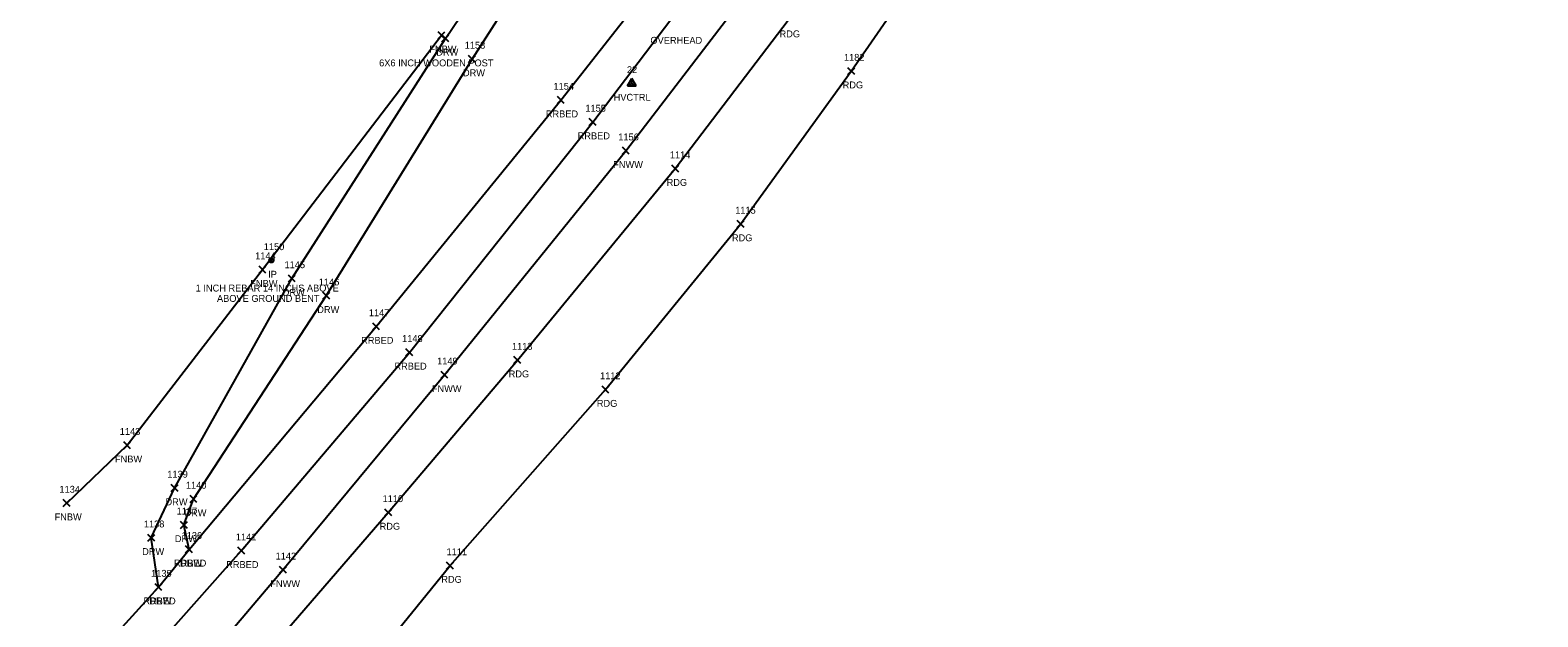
# Model space of a CAD drawing. Extents: x 1508122 to 1515053, y 865012 to 875267.
# Drawn here: x 1509138.2 to 1509575.3, y 866097.6 to 866267.8 of the extents above; entities that cross this region are included whole.
import ezdxf

# ---------------------------------------------------------------- set-up
doc = ezdxf.new("R2010")
doc.units = 0
for name, color, linetype in [('C_A', 7, 'Continuous'), ('C_I', 7, 'Continuous'), ('CPSM', 7, 'Continuous'), ('L_A', 7, 'Continuous'), ('L_C', 7, 'Continuous'), ('L_I', 7, 'Continuous'), ('L_TIC', 7, 'Continuous'), ('LFNC', 7, 'Continuous'), ('M_A', 7, 'Continuous'), ('M_C', 7, 'Continuous'), ('M_I', 7, 'Continuous'), ('MPIR', 7, 'Continuous'), ('P_A', 7, 'Continuous'), ('P_I', 7, 'Continuous'), ('P_TIC', 7, 'Continuous'), ('PEU', 7, 'Continuous'), ('R_A', 7, 'Continuous'), ('R_I', 7, 'Continuous'), ('R_TIC', 7, 'Continuous'), ('RDW', 7, 'Continuous'), ('RRB', 7, 'Continuous'), ('U_A', 7, 'Continuous')]:
    doc.layers.add(name, color=color, linetype=linetype)

msp = doc.modelspace()

# ---------------------------------------------------------------- linework, layer by layer
at = {"layer": 'CPSM'}
for p, q in [((1509311.42, 866251.58), (1509312.67, 866253.74)), ((1509313.92, 866251.58), (1509312.67, 866253.74)), ((1509312.68, 866252.3), (1509312.67, 866253.74)), ((1509311.42, 866251.58), (1509312.68, 866252.3)), ((1509311.42, 866251.58), (1509313.92, 866251.58)), ((1509312.68, 866252.3), (1509312.68, 866252.3)), ((1509312.68, 866252.3), (1509313.92, 866251.58))]:
    msp.add_line(p, q, dxfattribs=at)
at = {"layer": 'L_TIC'}
for points in [[(1509256.48, 866265.27), (1509258.48, 866267.27)], [(1509258.48, 866265.27), (1509256.48, 866267.27)], [(1509309.89, 866231.8), (1509311.89, 866233.8)], [(1509311.89, 866231.8), (1509309.89, 866233.8)], [(1509204.58, 866197.32), (1509206.58, 866199.32)], [(1509206.58, 866197.32), (1509204.58, 866199.32)], [(1509257.33, 866166.82), (1509259.33, 866168.82)], [(1509259.33, 866166.82), (1509257.33, 866168.82)], [(1509165.34, 866146.4), (1509167.34, 866148.4)], [(1509167.34, 866146.4), (1509165.34, 866148.4)], [(1509147.84, 866129.63), (1509149.84, 866131.63)], [(1509149.84, 866129.63), (1509147.84, 866131.63)], [(1509210.5, 866110.27), (1509212.5, 866112.27)], [(1509212.5, 866110.27), (1509210.5, 866112.27)]]:
    msp.add_lwpolyline(points, dxfattribs=at)
at = {"layer": 'LFNC'}
for points in [[(1508724.58, 865616.04), (1508798.39, 865687.75), (1508875.38, 865763.51), (1508931.23, 865818.85), (1508982.18, 865869.29), (1509035.45, 865924.1), (1509094.95, 865982.16), (1509139.87, 866027.02), (1509167.95, 866059.98), (1509211.5, 866111.27), (1509258.33, 866167.82), (1509310.89, 866232.8), (1509348.98, 866282.54), (1509409.27, 866365.5), (1509441.91, 866414.7), (1509478.64, 866471.59), (1509510.32, 866522.25)], [(1509148.84, 866130.63), (1509166.34, 866147.4), (1509205.58, 866198.32), (1509257.48, 866266.27)]]:
    msp.add_lwpolyline(points, dxfattribs=at)
at = {"layer": 'MPIR'}
for radius in [0.625, 0.0833]:
    msp.add_circle((1509208.16, 866200.98), radius, dxfattribs=at)
at = {"layer": 'P_TIC'}
for points in [[(1509375.26, 866254.88), (1509377.26, 866256.88)], [(1509377.26, 866254.88), (1509375.26, 866256.88)], [(1509324.23, 866226.62), (1509326.23, 866228.62)], [(1509326.23, 866226.62), (1509324.23, 866228.62)], [(1509343.16, 866210.55), (1509345.16, 866212.55)], [(1509345.16, 866210.55), (1509343.16, 866212.55)], [(1509278.45, 866171.09), (1509280.45, 866173.09)], [(1509280.45, 866171.09), (1509278.45, 866173.09)], [(1509304, 866162.55), (1509306, 866164.55)], [(1509306, 866162.55), (1509304, 866164.55)], [(1509241.04, 866126.91), (1509243.04, 866128.91)], [(1509243.04, 866126.91), (1509241.04, 866128.91)], [(1509258.93, 866111.51), (1509260.93, 866113.51)], [(1509260.93, 866111.51), (1509258.93, 866113.51)]]:
    msp.add_lwpolyline(points, dxfattribs=at)
at = {"layer": 'PEU'}
for points in [[(1508834.79, 865646.55), (1508872.67, 865695.62), (1508920.37, 865755), (1508947.99, 865790.47), (1508992.59, 865844.04), (1509029.62, 865887.05), (1509074.71, 865938.15), (1509076.21, 865938.91), (1509118.9, 865986.57), (1509166.14, 866040.81), (1509208.36, 866088.99), (1509242.04, 866127.91), (1509279.45, 866172.09), (1509325.23, 866227.62), (1509357.97, 866270.69), (1509379.31, 866300.93), (1509415.81, 866351.46), (1509451.5, 866409.82), (1509485.86, 866467.6), (1509516.97, 866520.33), (1509530.58, 866543.24), (1509548.88, 866575.75)], [(1508854.52, 865631.8), (1508891.73, 865680.86), (1508929.69, 865727.93), (1508966.84, 865774.38), (1509011.87, 865829.05), (1509047.63, 865870.06), (1509091.96, 865920.06), (1509093.12, 865920.34), (1509137.51, 865972.18), (1509182.39, 866021.44), (1509229.98, 866075.59), (1509259.93, 866112.51), (1509305, 866163.55), (1509344.16, 866211.55), (1509376.26, 866255.88), (1509408.52, 866302.52), (1509434.14, 866340.77), (1509471.53, 866399.58), (1509505.51, 866456.15), (1509544.81, 866522.39), (1509575.28, 866574.69)]]:
    msp.add_lwpolyline(points, dxfattribs=at)
at = {"layer": 'R_TIC'}
for points in [[(1509257.58, 866264.37), (1509259.58, 866266.37)], [(1509259.58, 866264.37), (1509257.58, 866266.37)], [(1509265.32, 866258.4), (1509267.32, 866260.4)], [(1509267.32, 866258.4), (1509265.32, 866260.4)], [(1509291.05, 866246.49), (1509293.05, 866248.49)], [(1509293.05, 866246.49), (1509291.05, 866248.49)], [(1509300.29, 866240.12), (1509302.29, 866242.12)], [(1509302.29, 866240.12), (1509300.29, 866242.12)], [(1509213.09, 866194.75), (1509215.09, 866196.75)], [(1509215.09, 866194.75), (1509213.09, 866196.75)], [(1509223.08, 866189.75), (1509225.08, 866191.75)], [(1509225.08, 866189.75), (1509223.08, 866191.75)], [(1509237.52, 866180.83), (1509239.52, 866182.83)], [(1509239.52, 866180.83), (1509237.52, 866182.83)], [(1509247.17, 866173.34), (1509249.17, 866175.34)], [(1509249.17, 866173.34), (1509247.17, 866175.34)], [(1509179.1, 866133.99), (1509181.1, 866135.99)], [(1509181.1, 866133.99), (1509179.1, 866135.99)], [(1509184.58, 866130.81), (1509186.58, 866132.81)], [(1509186.58, 866130.81), (1509184.58, 866132.81)], [(1509181.8, 866123.3), (1509183.8, 866125.3)], [(1509183.8, 866123.3), (1509181.8, 866125.3)], [(1509172.32, 866119.57), (1509174.32, 866121.57)], [(1509174.32, 866119.57), (1509172.32, 866121.57)], [(1509183.3, 866116.22), (1509185.3, 866118.22)], [(1509185.3, 866116.22), (1509183.3, 866118.22)], [(1509183.3, 866116.22), (1509185.3, 866118.22)], [(1509185.3, 866116.22), (1509183.3, 866118.22)], [(1509198.41, 866115.81), (1509200.41, 866117.81)], [(1509200.41, 866115.81), (1509198.41, 866117.81)], [(1509174.42, 866105.26), (1509176.42, 866107.26)], [(1509176.42, 866105.26), (1509174.42, 866107.26)], [(1509174.42, 866105.26), (1509176.42, 866107.26)], [(1509176.42, 866105.26), (1509174.42, 866107.26)]]:
    msp.add_lwpolyline(points, dxfattribs=at)
at = {"layer": 'RDW'}
for points in [[(1509175.42, 866106.26), (1509173.32, 866120.57), (1509180.1, 866134.99), (1509214.09, 866195.75), (1509258.58, 866265.37), (1509297.47, 866322.84), (1509353.91, 866405.07), (1509385.61, 866444.81), (1509414.73, 866486.92), (1509438.11, 866515.54), (1509448.72, 866529.31), (1509457.68, 866545.56), (1509464.46, 866541.85)], [(1509184.3, 866117.22), (1509182.8, 866124.3), (1509185.58, 866131.81), (1509224.08, 866190.75), (1509266.32, 866259.4), (1509302.94, 866316.58), (1509358.12, 866400.23), (1509391.86, 866440.27), (1509422.23, 866480.4), (1509444.66, 866510.88), (1509457.51, 866527.21), (1509464.46, 866541.85)]]:
    msp.add_lwpolyline(points, dxfattribs=at)
at = {"layer": 'RRB'}
for points in [[(1508639.82, 865572.96), (1508703.07, 865634.54), (1508776.82, 865704.61), (1508856.34, 865784.12), (1508912.2, 865838.55), (1508964.7, 865888.82), (1509016.49, 865939.79), (1509080.96, 866005.09), (1509118.28, 866044.61), (1509147.09, 866075.05), (1509175.42, 866106.26), (1509184.3, 866117.22), (1509238.52, 866181.83), (1509292.05, 866247.49), (1509330.87, 866297), (1509389.52, 866377.79), (1509421.76, 866425.85), (1509457.91, 866484.5), (1509492.63, 866543.56), (1509498.04, 866553.04), (1509526.06, 866605.21)], [(1508711.19, 865626.15), (1508783.92, 865697.13), (1508865.8, 865776.48), (1508920.93, 865830.03), (1508972.14, 865881.23), (1509024.12, 865931.95), (1509088.71, 865997.8), (1509126.76, 866037.79), (1509155.51, 866067.3), (1509199.41, 866116.81), (1509248.17, 866174.34), (1509301.29, 866241.12), (1509339.25, 866291.04), (1509399.39, 866372.51), (1509432.54, 866419.84), (1509467.99, 866478.89), (1509502.81, 866537.91), (1509508.47, 866548.76), (1509536.84, 866601.03)]]:
    msp.add_lwpolyline(points, dxfattribs=at)

# ---------------------------------------------------------------- texts
at = {"layer": 'C_A'}
msp.add_text('HVCTRL', height=2, dxfattribs=at).set_placement((1509307.37, 866247.3))
at = {"layer": 'C_I'}
msp.add_text('22', height=2, dxfattribs=at).set_placement((1509311.21, 866255.3))
at = {"layer": 'L_A'}
for s, p in [('FNBW', (1509253.95, 866261.27)), ('FNWW', (1509307.24, 866227.8)), ('FNBW', (1509202.05, 866193.32)), ('FNWW', (1509254.68, 866162.82)), ('FNBW', (1509162.81, 866142.4)), ('FNBW', (1509145.31, 866125.63)), ('FNWW', (1509207.85, 866106.27))]:
    msp.add_text(s, height=2, dxfattribs=at).set_placement(p)
at = {"layer": 'L_C'}
msp.add_text('6X6 INCH WOODEN POST', height=2, dxfattribs=at).set_placement((1509239.39, 866257.27))
at = {"layer": 'L_I'}
for s, p in [('1156', (1509308.71, 866235.8)), ('1144', (1509203.45, 866201.32)), ('1149', (1509256.2, 866170.82)), ('1143', (1509164.21, 866150.4)), ('1134', (1509146.71, 866133.63)), ('1142', (1509209.38, 866114.27))]:
    msp.add_text(s, height=2, dxfattribs=at).set_placement(p)
at = {"layer": 'M_A'}
msp.add_text('IP', height=2, dxfattribs=at).set_placement((1509207.21, 866195.98))
at = {"layer": 'M_C'}
for s, p in [('1 INCH REBAR 14 INCHS ABOVE', (1509186.21, 866191.98)), ('ABOVE GROUND BENT', (1509192.39, 866188.98))]:
    msp.add_text(s, height=2, dxfattribs=at).set_placement(p)
at = {"layer": 'M_I'}
msp.add_text('1150', height=2, dxfattribs=at).set_placement((1509205.95, 866203.98))
at = {"layer": 'P_A'}
for p in [(1509355.46, 866265.69), (1509373.75, 866250.88), (1509322.72, 866222.62), (1509341.65, 866206.55), (1509276.94, 866167.09), (1509302.49, 866158.55), (1509239.53, 866122.91), (1509257.41, 866107.51)]:
    msp.add_text('RDG', height=2, dxfattribs=at).set_placement(p)
at = {"layer": 'P_I'}
for s, p in [('1182', (1509374.13, 866258.88)), ('1114', (1509323.67, 866230.62)), ('1115', (1509342.6, 866214.55)), ('1113', (1509277.89, 866175.09)), ('1112', (1509303.44, 866166.55)), ('1110', (1509240.4, 866130.91)), ('1111', (1509258.93, 866115.51))]:
    msp.add_text(s, height=2, dxfattribs=at).set_placement(p)
at = {"layer": 'R_A'}
for s, p in [('DRW', (1509255.95, 866260.37)), ('DRW', (1509263.69, 866254.4)), ('RRBED', (1509287.7, 866242.49)), ('RRBED', (1509296.94, 866236.12)), ('DRW', (1509211.46, 866190.75)), ('DRW', (1509221.45, 866185.75)), ('RRBED', (1509234.17, 866176.83)), ('RRBED', (1509243.82, 866169.34)), ('DRW', (1509177.47, 866129.99)), ('DRW', (1509182.95, 866126.81)), ('DRW', (1509170.69, 866115.57)), ('DRW', (1509180.17, 866119.3)), ('RRBED', (1509179.94, 866112.22)), ('DRW', (1509181.67, 866112.22)), ('RRBED', (1509195.06, 866111.81)), ('RRBED', (1509171.06, 866101.26)), ('DRW', (1509172.79, 866101.26))]:
    msp.add_text(s, height=2, dxfattribs=at).set_placement(p)
at = {"layer": 'R_I'}
for s, p in [('1153', (1509264.2, 866262.4)), ('1154', (1509289.93, 866250.49)), ('1155', (1509299.17, 866244.12)), ('1145', (1509211.97, 866198.75)), ('1146', (1509221.9, 866193.75)), ('1147', (1509236.4, 866184.83)), ('1148', (1509246.04, 866177.34)), ('1139', (1509177.97, 866137.99)), ('1140', (1509183.37, 866134.81)), ('1137', (1509180.68, 866127.3)), ('1138', (1509171.19, 866123.57)), ('1136', (1509182.12, 866120.22)), ('1136', (1509182.12, 866120.22)), ('1141', (1509197.85, 866119.81)), ('1135', (1509173.29, 866109.26)), ('1135', (1509173.29, 866109.26))]:
    msp.add_text(s, height=2, dxfattribs=at).set_placement(p)
at = {"layer": 'U_A'}
msp.add_text('OVERHEAD', height=2, dxfattribs=at).set_placement((1509318.03, 866263.82))

doc.saveas('drawing.dxf')
